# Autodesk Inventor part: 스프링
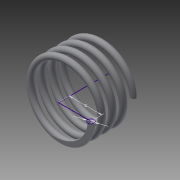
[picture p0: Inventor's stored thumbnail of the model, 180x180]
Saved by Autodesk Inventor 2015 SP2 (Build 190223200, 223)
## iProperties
Created: 2015-06
Part Number: 스프링
Material: 일반
Document SubType Name: Modeling
Designer: AMC
Density: 1 g/cm^3
Appearance: 기본값
Mass: 0.344746 g
Surface Area: 9.40933 cm^2
Volume: 0.344746 cm^3
Author: AMC
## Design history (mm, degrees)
sketch "스케치1"
  geometry: L1 (0, 0)-(8, 0); L2 (0, 0)-(0, 14.102); C1 r 0.75 at (8, 0)
  constraints: 4 end point, 1 centre point, 1 coincident, 1 horizontal, 1 vertical
  dimensions: "d0" = 8 distance of L1.start L1.end; "d1" = 1.5 diameter of C1
feature "코일1" sketch "스케치1" pitch "d2" = 10; turns "d4" = 4; dims "d3" = 10.5 (= a), "d5" = 0, angle "d6" = 90 deg, angle "d7" = 90 deg, "d8" = 0, "d9" = 0
sketch "스케치2"
  geometry: L1 (2.181, 0)-(-17.271, 0); L2 (-17.271, 0)-(-17.271, -4.707); L3 (-17.271, -4.707)-(2.181, -4.707); L4 (2.181, -4.707)-(2.181, 0); L5 (3.025, 10.5)-(-21.212, 10.5); L6 (-21.212, 10.5)-(-21.212, 15.441); L7 (-21.212, 15.441)-(3.025, 15.441); L8 (3.025, 15.441)-(3.025, 10.5); C1 r 0.75 at (0, 0) reference; C2 r 0.75 at (0, 10.5) reference; 8 further points
  constraints: 16 end point, 4 parallel, 2 horizontal, 2 perpendicular, 1 point on line, 7 other
  dimensions: "d10" = 10.5 distance between parallel lines of L1 L5 (= a)
extrude "돌출1" cut sketch "스케치2" stored distance "d11" = 50; taper "d12" = 0 deg
node "솔리드1"
node "절단 모서리 투영1"
other parameters: "a" = 10.5 [user parameter; used in 2 equation terms]
